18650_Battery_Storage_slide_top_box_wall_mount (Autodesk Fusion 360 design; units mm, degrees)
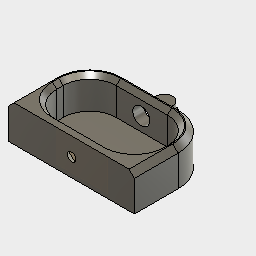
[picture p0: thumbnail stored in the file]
sketch "Skizze1" plane through (0, 0, 0) normal (0, 1, 0) x axis (1, 0, 0)
  line L1 (49, 0) -> (0, 0)
  line L2 (49, -28) -> (49, 0)
  line L3 (0, -28) -> (49, -28)
  line L4 (0, 0) -> (0, -28)
  point P2 (0, 0)
  point P5 (0, -28)
  dimension "d1" distance P2 P5 = 28
extrude "Extrusion1" new body sketch "Skizze1" along normal blind 12
shell "Schale" outerThickness 5
fillet "Abrundung1" radius 12.5
extrude "Extrusion2" cut of existing geometry blind -3
sketch "Skizze2" plane through (0, 0, 0) normal (0, 1, 0) x axis (1, 0, 0)
sketch "Skizze3" plane through (0, 0, 0) normal (0, 1, 0) x axis (1, 0, 0)
fillet "Abrundung2" radius 17.5
fillet "Abrundung3" radius 17.5
sketch "Skizze4" plane through (0, 0, 28) normal (0, 0, -1) x axis (-1, 0, 0)
  line L1 (-12.5, 12) -> (-12.5, -3)
  line L2 (-36.5, 12) -> (-12.5, 12)
  line L3 (-36.5, -3) -> (-36.5, 12)
  line L4 (-12.5, -3) -> (-36.5, -3)
move "Verschieben"
sketch "Skizze5" plane through (0, 0, 33) normal (0, 0, 1) x axis (1, 0, 0)
  line L1 (54, 0) -> (-5, 0)
  line L2 (54, 17) -> (54, 0)
  line L3 (-5, 17) -> (54, 17)
  line L4 (-5, 0) -> (-5, 17)
  circle C1 centre (24.5, 8.5) radius 2
  dimension "d10" diameter C1 = 4
extrude "Extrusion3" cut sketch "Skizze5" profile of C1 against normal blind 6
chamfer "Fase1" distance 5
sketch "Skizze6" plane through (0, 0, -5) normal (0, 0, -1) x axis (-1, 0, 0)
  line L1 (-12.5, 17) -> (-12.5, 0)
  line L2 (-36.5, 17) -> (-12.5, 17)
  line L3 (-36.5, 0) -> (-36.5, 17)
  line L4 (-12.5, 0) -> (-36.5, 0)
  circle C1 centre (-24.255, 8.5) radius 4
  dimension "d14" diameter C1 = 8
extrude "Extrusion4" cut sketch "Skizze6" profile of C1 against normal blind 19
sketch "Skizze7" plane through (0, 0, 0) normal (0, 1, 0) x axis (1, 0, 0)
  circle C1 centre (20, 15) radius 5
  dimension "d17" diameter C1 = 10
extrude "Extrusion5" new body sketch "Skizze7" along normal blind 0.5
sketch "Skizze8" plane through (0, 0.5, 0) normal (0, 1, 0) x axis (-1, 0, 0)
  circle C1 centre (-20, -15) radius 5
  circle C2 centre (-20, -15) radius 3.9
  dimension "d20" diameter C2 = 7.8
extrude "Extrusion6" add sketch "Skizze8" profile of C2 along normal blind 4.5
chamfer "Fase2" distance 2
chamfer "Fase3" distance 2.5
